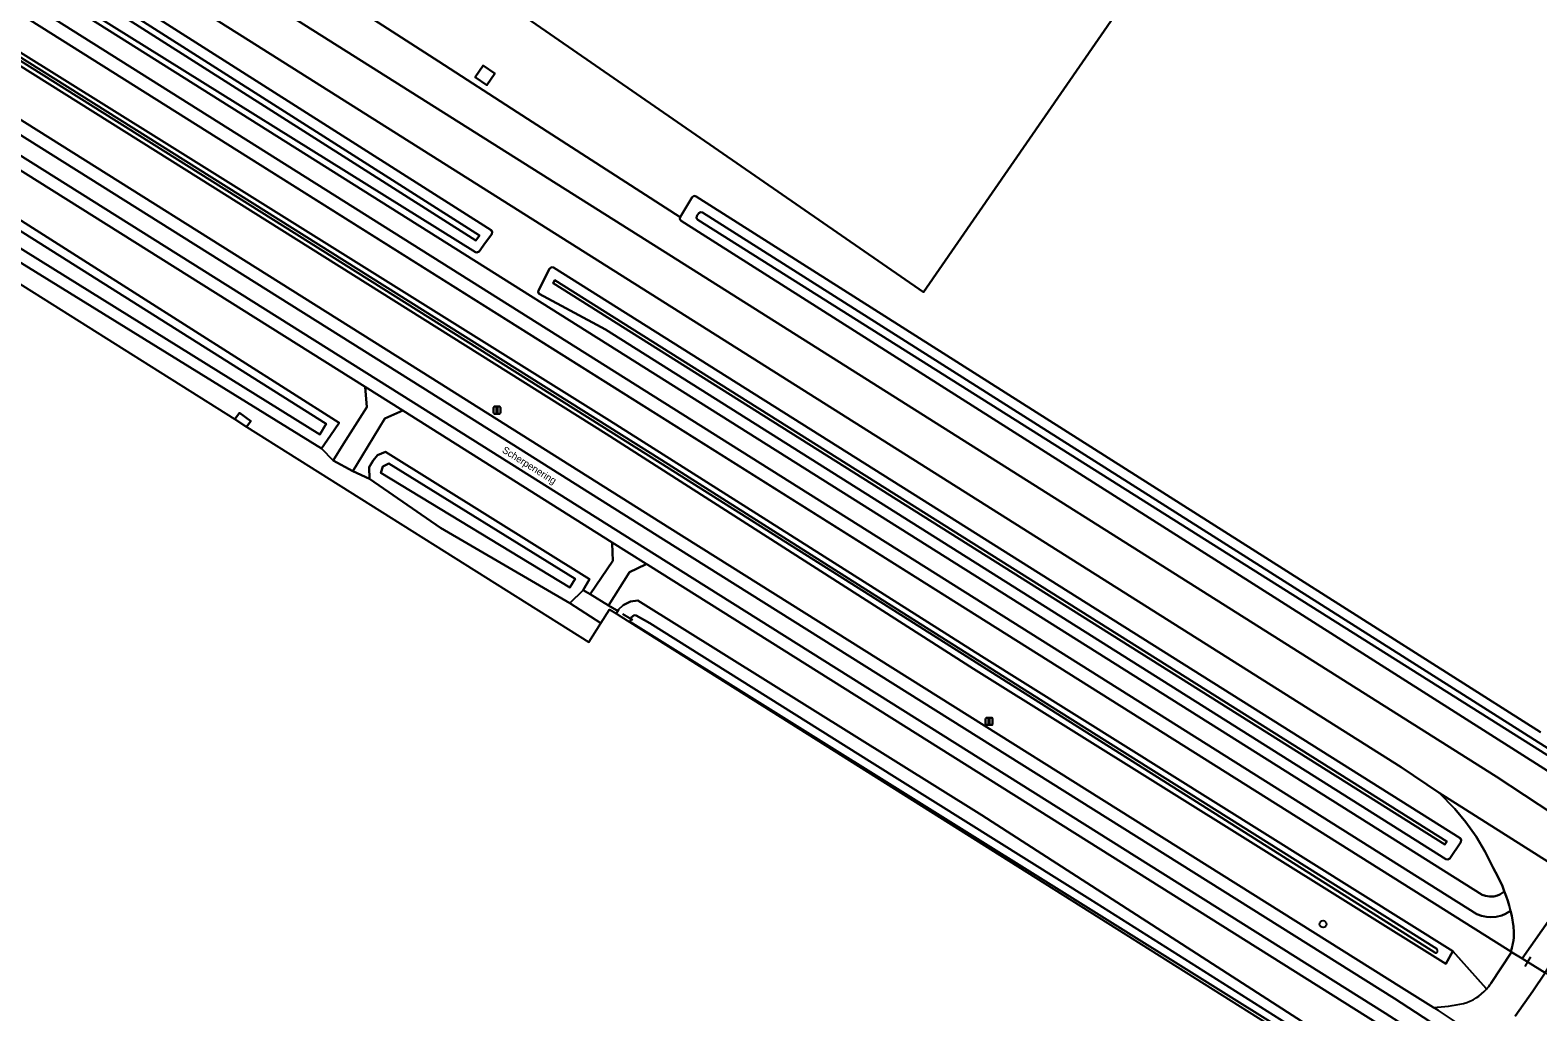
# Model space of a CAD drawing. Extents: x 152881 to 155736, y 382924 to 386919.
# Drawn here: x 153064.6 to 153277.6, y 383016.9 to 383155.6 of the extents above; entities that cross this region are included whole.
import ezdxf

# ---------------------------------------------------------------- set-up
doc = ezdxf.new("R2010")
doc.units = 0
for name, color, linetype in [('IMGEO_Berm_groen', 7, 'Continuous'), ('IMGEO_Boom', 7, 'Continuous'), ('IMGEO_Duiker', 7, 'Continuous'), ('IMGEO_Groenvoorziening', 7, 'Continuous'), ('IMGEO_Hek', 7, 'Continuous'), ('IMGEO_Lichtmast', 7, 'Continuous'), ('IMGEO_Oever', 7, 'Continuous'), ('IMGEO_Openbare_ruimte_label', 7, 'Continuous'), ('IMGEO_Rijbaan_lokaal_gesloten', 7, 'Continuous'), ('IMGEO_Rijbaan_lokaal_open', 7, 'Continuous'), ('IMGEO_Sloot', 7, 'Continuous'), ('IMGEO_Terreindeel_gesloten', 7, 'Continuous'), ('IMGEO_Terreindeel_onvherhard', 7, 'Continuous'), ('IMGEO_Waterloop', 7, 'Continuous')]:
    doc.layers.add(name, color=color, linetype=linetype)

msp = doc.modelspace()

# ---------------------------------------------------------------- linework, layer by layer
at = {"layer": 'IMGEO_Berm_groen'}
msp.add_lwpolyline([(153145.22, 383071.86), (153146.43, 383073.79), (153147.39, 383073.19), (153147.6, 383073.55), (153147.4, 383073.67), (153146.3, 383074.34), (153143.71, 383075.93), (153142.71, 383076.51), (153140.83, 383074.66)], close=True, dxfattribs=at)
at = {"layer": 'IMGEO_Boom'}
msp.add_circle((153247.26, 383029.32), 0.489, dxfattribs=at)
at = {"layer": 'IMGEO_Duiker'}
msp.add_lwpolyline([(153148.25, 383073.16), (153149.66, 383072.31)], dxfattribs=at)
at = {"layer": 'IMGEO_Groenvoorziening'}
for points in [[(153270.96, 383020.95), (153273.9, 383025.38), (153273.81, 383025.44), (153273.05, 383025.91), (153030.73, 383178.33), (152959.64, 383223.14), (152933.46, 383239.65), (152928.97, 383247.39), (152928.17, 383250), (152926.53, 383255.4), (152926.3, 383256.13), (152927.9, 383267.67), (152937.99, 383340.71), (152944.2, 383369.81), (152955.53, 383400.99), (152969.74, 383429.27), (152974.63, 383436.64), (152983.1, 383449.09), (153167.02, 383706.28)], [(153270.36, 383020.15), (153270.3, 383020.23), (153265.62, 383025.5), (153264.61, 383023.7), (153197.89, 383065.4), (153145.97, 383098.58), (153082.25, 383138.58), (153000, 383190.23), (152959.15, 383215.88), (152928.25, 383235.62), (152928.76, 383236.26), (152929.29, 383236.92), (152923.76, 383241.92)], [(152923.76, 383241.92), (152929.29, 383236.92), (152960.62, 383216.52), (153000, 383191.92), (153083.11, 383140.01), (153146.41, 383100.47), (153199.01, 383067.2), (153265.62, 383025.5), (153270.3, 383020.23), (153270.36, 383020.15)], [(152921, 383232.83), (152920.73, 383232.47), (152974.17, 383198.93), (153121.08, 383106.58), (153154.94, 383085.28), (153258.36, 383020.37), (153262.88, 383017.55)], [(153002.4, 383201.71), (153269.76, 383033.47), (153270.23, 383033.3), (153270.78, 383033.2), (153271.4, 383033.23), (153271.92, 383033.36), (153272.25, 383033.51), (153272.67, 383033.78), (153272.88, 383033.96), (153272.61, 383034.66), (153271.96, 383036.05), (153271.63, 383036.68), (153271.29, 383037.28), (153270.17, 383039.54), (153268.88, 383041.71), (153267.46, 383043.72), (153265.89, 383045.63), (153263.65, 383047.85), (153258.32, 383051.48), (153095.4, 383154.22), (153012.06, 383206.63)], [(153247.65, 383200.89), (153190.8, 383118.62), (153092.29, 383186.7)], [(153278.99, 383050.98), (153237.4, 383077.41), (153156.56, 383128.66), (153156.39, 383128.91), (153156.43, 383129.21), (153133.39, 383144.04), (153122.32, 383151.17), (153085.36, 383174.95)], [(153085.36, 383174.95), (153122.32, 383151.17), (153133.39, 383144.04), (153156.43, 383129.21), (153158.13, 383132.01), (153158.38, 383132.19), (153158.69, 383132.14), (153239.69, 383080.75), (153277.97, 383056.46)], [(153083.88, 383168.64), (153153.92, 383124.47), (153271.72, 383050.18), (153279.75, 383044.92)], [(153070.92, 383164.74), (153129.69, 383127.38), (153129.87, 383127.11), (153129.8, 383126.8), (153128.92, 383125.61), (153128.01, 383124.37), (153127.68, 383124.21), (153127.48, 383124.27), (153068.18, 383161.24)], [(153151.62, 383080.21), (153151.5, 383080.15), (153149.27, 383079.03), (153146.3, 383074.34), (153147.4, 383073.67), (153147.6, 383073.55), (153147.71, 383073.75), (153148.36, 383074.38), (153149.4, 383074.91), (153150.43, 383075.06), (153199.05, 383044.71), (153261.96, 383004.15), (153263.75, 383002.45), (153265.3, 383000.65)], [(153259.85, 383011.68), (153260.11, 383012.04), (153255.3, 383015.08), (153151.84, 383080.07), (153151.62, 383080.21)], [(153284.16, 383000), (153285.11, 383013.48), (153285.32, 383016.39), (153286.97, 383014.98), (153287.1, 383017.12), (153279.29, 383022.07), (153278.65, 383022.46), (153276.89, 383019.83), (153274.4, 383016.31)]]:
    msp.add_lwpolyline(points, dxfattribs=at)
for points in [[(153190.8, 383118.62), (153247.65, 383200.89), (153132.48, 383280.48), (153075.62, 383198.22), (153089.84, 383188.39), (153089.92, 383188.51), (153092.37, 383186.82), (153092.29, 383186.7)], [(153270.35, 383030.34), (153269.65, 383030.5), (153268.98, 383030.75), (153000.84, 383199.48), (152960.77, 383224.74), (152959.93, 383223.55), (152959.64, 383223.14), (153030.73, 383178.33), (153273.05, 383025.91), (153273.81, 383025.44), (153273.95, 383025.91), (153274.09, 383026.56), (153274.16, 383027), (153274.21, 383027.44), (153274.23, 383028.21), (153274.18, 383028.98), (153273.93, 383030.47), (153273.74, 383031.21), (153273.05, 383030.78), (153272.51, 383030.56), (153271.72, 383030.36), (153270.97, 383030.3)], [(153000.4, 383175.26), (153000, 383175.07), (152998.15, 383174.21), (152994.7, 383168.72), (152993.1, 383166.16), (152994.67, 383165.11), (152996.32, 383167.7), (152997.95, 383170.27), (153000, 383168.97), (153072.65, 383122.76), (153108.22, 383100.14), (153107, 383098.37), (153105.73, 383096.53), (153107.36, 383094.81), (153108.86, 383097.18), (153112.14, 383102.37), (153111.89, 383105.21)], [(153130.2, 383149.49), (153129.08, 383147.86), (153127.44, 383148.99), (153128.57, 383150.62)], [(153136.5, 383118.37), (153136.36, 383118.6), (153136.39, 383118.86), (153137.96, 383121.92), (153138.21, 383122.13), (153138.53, 383122.08), (153217.59, 383072.33), (153266.62, 383041.47), (153266.8, 383041.22), (153266.74, 383040.91), (153265.17, 383038.6), (153264.92, 383038.43), (153264.63, 383038.48), (153145.85, 383113.34)], [(153117.21, 383101.88), (153114.66, 383100.74), (153111.49, 383095.5), (153110.15, 383093.3), (153112.51, 383092.25), (153112.48, 383093.86), (153113.04, 383094.8), (153113.64, 383095.59), (153114.75, 383096.04), (153143.59, 383078.07), (153142.71, 383076.51), (153143.71, 383075.93), (153146.89, 383080.65), (153146.82, 383083.09), (153146.82, 383083.24)]]:
    msp.add_lwpolyline(points, close=True, dxfattribs=at)
for centre, radius, start, end in [((153265.44, 383024.44), 6.54, 284.7663, 318.893), ((153265.59, 383024.33), 6.35, 318.7416, 327.7708), ((153261.86, 383040.75), 23.22, 272.4991, 283.0433)]:
    msp.add_arc(centre, radius, start, end, dxfattribs=at)
at = {"layer": 'IMGEO_Hek'}
for points in [[(152959.64, 383223.14), (153030.73, 383178.33), (153142.93, 383107.76), (153273.05, 383025.91)], [(153273.05, 383025.91), (153273.81, 383025.44)], [(153273.81, 383025.44), (153275.42, 383024.45)], [(153275.42, 383024.45), (153276.17, 383023.99)], [(153276.56, 383024.63), (153276.17, 383023.99)], [(153276.17, 383023.99), (153275.77, 383023.35)], [(153276.17, 383023.99), (153278.65, 383022.46)]]:
    msp.add_lwpolyline(points, dxfattribs=at)
at = {"layer": 'IMGEO_Lichtmast'}
for p, q in [((153130.03, 383101.53), (153130.03, 383102.33)), ((153130.03, 383102.33), (153130.03, 383101.53)), ((153130.13, 383102.43), (153130.92, 383102.43)), ((153130.92, 383102.43), (153130.13, 383102.43)), ((153130.92, 383101.43), (153130.13, 383101.43)), ((153130.13, 383101.43), (153130.92, 383101.43)), ((153131.02, 383102.33), (153131.02, 383101.53)), ((153131.02, 383101.53), (153131.02, 383102.33)), ((153199.68, 383058.46), (153200.47, 383058.46)), ((153200.47, 383058.46), (153199.68, 383058.46)), ((153199.58, 383057.56), (153199.58, 383058.36)), ((153199.58, 383058.36), (153199.58, 383057.56)), ((153200.47, 383057.46), (153199.68, 383057.46)), ((153199.68, 383057.46), (153200.47, 383057.46)), ((153200.57, 383058.36), (153200.57, 383057.56)), ((153200.57, 383057.56), (153200.57, 383058.36))]:
    msp.add_line(p, q, dxfattribs=at)
for points in [[(153130.45, 383102.31), (153130.6, 383102.31), (153130.6, 383101.56), (153130.45, 383101.56), (153130.45, 383102.31)], [(153200, 383058.33), (153200.15, 383058.33), (153200.15, 383057.58), (153200, 383057.58), (153200, 383058.33)]]:
    msp.add_lwpolyline(points, dxfattribs=at)
for centre, start, end in [((153130.13, 383102.33), 90, 180), ((153130.13, 383102.33), 90, 180), ((153130.13, 383101.53), 180, 270), ((153130.13, 383101.53), 180, 270), ((153130.92, 383102.33), 0, 90), ((153130.92, 383102.33), 360, 90), ((153130.92, 383101.53), 270, 0), ((153130.92, 383101.53), 270, 0), ((153199.68, 383058.36), 90, 180), ((153199.68, 383058.36), 90, 180), ((153200.47, 383058.36), 0, 90), ((153200.47, 383058.36), 360, 90), ((153199.68, 383057.56), 180, 270), ((153199.68, 383057.56), 180, 270), ((153200.47, 383057.56), 270, 0), ((153200.47, 383057.56), 270, 0)]:
    msp.add_arc(centre, 0.1, start, end, dxfattribs=at)
at = {"layer": 'IMGEO_Oever'}
for points in [[(152929.29, 383236.92), (152928.76, 383236.26), (152928.25, 383235.62), (152959.15, 383215.88), (153000, 383190.23), (153082.25, 383138.58), (153145.97, 383098.58), (153197.89, 383065.4), (153264.61, 383023.7), (153265.62, 383025.5), (153199.01, 383067.2), (153146.41, 383100.47), (153083.11, 383140.01), (153000, 383191.92), (152960.62, 383216.52)], [(153107, 383098.37), (153108.22, 383100.14), (153072.65, 383122.76), (153000, 383168.97), (152997.95, 383170.27), (152996.32, 383167.7), (152994.67, 383165.11), (152995.37, 383164.68), (152998.84, 383162.53), (153105.73, 383096.53)], [(152998.64, 383167.94), (153106.4, 383099.98), (153105.5, 383098.51), (153002.71, 383162.42), (152997.61, 383166.25)], [(153136.5, 383118.37), (153145.85, 383113.34), (153264.63, 383038.48), (153264.92, 383038.43), (153265.17, 383038.6), (153266.74, 383040.91), (153266.8, 383041.22), (153266.62, 383041.47), (153217.59, 383072.33), (153138.53, 383122.08), (153138.21, 383122.13), (153137.96, 383121.92), (153136.39, 383118.86), (153136.36, 383118.6)], [(153214.55, 383071.99), (153138.48, 383119.87), (153138.71, 383120.32), (153215.57, 383071.94), (153264.74, 383041), (153264.46, 383040.58)], [(153142.71, 383076.51), (153143.59, 383078.07), (153114.75, 383096.04), (153113.64, 383095.59), (153113.04, 383094.8), (153112.48, 383093.86), (153112.51, 383092.25), (153122.53, 383085.33), (153140.83, 383074.66)], [(153115.24, 383094.39), (153141.57, 383078.08), (153140.81, 383076.86), (153114.13, 383093.08), (153114.4, 383093.98)]]:
    msp.add_lwpolyline(points, close=True, dxfattribs=at)
for points in [[(153263.04, 383025.3), (153208.01, 383060.1), (153183.34, 383075.7), (153153.59, 383094.51), (153050.85, 383159.03), (152960.36, 383215.82), (152940.52, 383228.58), (152929.21, 383235.97)], [(152929.44, 383236.3), (152940.74, 383228.92), (152960.57, 383216.16), (153051.06, 383159.37), (153153.81, 383094.85), (153183.55, 383076.04), (153208.22, 383060.44), (153263.32, 383025.81)], [(153071.38, 383162.67), (153128.07, 383126.63), (153127.53, 383125.89), (153003.11, 383204.99)], [(153068.18, 383161.24), (153127.48, 383124.27), (153127.68, 383124.21), (153128.01, 383124.37), (153128.92, 383125.61), (153129.8, 383126.8), (153129.87, 383127.11), (153129.69, 383127.38), (153070.92, 383164.74)], [(153277.97, 383056.46), (153239.69, 383080.75), (153158.69, 383132.14), (153158.38, 383132.19), (153158.13, 383132.01), (153156.43, 383129.21), (153156.39, 383128.91), (153156.56, 383128.66), (153237.4, 383077.41), (153278.99, 383050.98)], [(153280.17, 383052.44), (153239.55, 383078.01), (153158.9, 383128.82), (153158.72, 383129.08), (153158.79, 383129.4), (153159.04, 383129.74), (153159.29, 383129.9), (153159.58, 383129.84), (153280.49, 383053.22)], [(153265.3, 383000.65), (153263.75, 383002.45), (153261.96, 383004.15), (153199.05, 383044.71), (153150.43, 383075.06), (153149.4, 383074.91), (153148.36, 383074.38), (153147.71, 383073.75), (153147.6, 383073.55), (153147.39, 383073.19)], [(153147.39, 383073.19), (153148.03, 383072.78), (153251.7, 383007.5)], [(153250.5, 383008.87), (153233.94, 383019.21), (153149.33, 383072.05), (153149.48, 383072.63), (153149.92, 383072.95), (153150.18, 383072.91), (153152.11, 383071.85), (153183.57, 383052.11), (153214.32, 383032.84), (153242.93, 383014.75)]]:
    msp.add_lwpolyline(points, dxfattribs=at)
msp.add_arc((153263.17, 383025.56), 0.292, 243.1895, 58.0522, dxfattribs=at)
at = {"layer": 'IMGEO_Rijbaan_lokaal_gesloten'}
for points in [[(153262.35, 383015.54), (153257.35, 383018.82), (153154.08, 383083.68), (153120.06, 383105.09), (152973.17, 383197.41), (152919.8, 383231.03)], [(152919.8, 383231.03), (152973.17, 383197.41), (153120.06, 383105.09), (153154.08, 383083.68), (153257.35, 383018.82), (153262.35, 383015.54)], [(153262.88, 383017.55), (153258.36, 383020.37), (153154.94, 383085.28), (153121.08, 383106.58), (152974.17, 383198.93), (152920.73, 383232.47)], [(152915.19, 383228.97), (152923.02, 383223.76), (152966.1, 383196.84), (152966.22, 383196.76), (152970.72, 383193.91), (152970.98, 383193.75), (152995.67, 383178.24), (153000.4, 383175.26), (153111.89, 383105.21), (153117.21, 383101.88), (153146.82, 383083.24), (153151.62, 383080.21), (153151.84, 383080.07), (153255.3, 383015.08), (153260.11, 383012.04)], [(153261.05, 383013.52), (153256.04, 383016.73), (153152.77, 383081.6), (153118.71, 383103), (152971.92, 383195.29), (152918.11, 383229.16)], [(152918.11, 383229.16), (152971.92, 383195.29), (153118.71, 383103), (153152.77, 383081.6), (153256.04, 383016.73), (153261.05, 383013.52)], [(153012.06, 383206.63), (153095.4, 383154.22), (153258.32, 383051.48), (153263.65, 383047.85), (153279.06, 383038.14)], [(153279.75, 383044.92), (153271.72, 383050.18), (153153.92, 383124.47), (153083.88, 383168.64)]]:
    msp.add_lwpolyline(points, dxfattribs=at)
msp.add_lwpolyline([(152960.77, 383224.74), (153000.84, 383199.48), (153268.98, 383030.75), (153269.65, 383030.5), (153270.35, 383030.34), (153270.97, 383030.3), (153271.72, 383030.36), (153272.51, 383030.56), (153273.05, 383030.78), (153273.74, 383031.21), (153273.57, 383031.94), (153273.37, 383032.6), (153273.15, 383033.26), (153272.88, 383033.96), (153272.67, 383033.78), (153272.25, 383033.51), (153271.92, 383033.36), (153271.4, 383033.23), (153270.78, 383033.2), (153270.23, 383033.3), (153269.76, 383033.47), (153002.4, 383201.71), (152962.33, 383226.97)], close=True, dxfattribs=at)
msp.add_arc((153248.03, 382992.08), 29.48, 33.5771, 59.7661, dxfattribs=at)
at = {"layer": 'IMGEO_Rijbaan_lokaal_open'}
for points in [[(153114.66, 383100.74), (153117.21, 383101.88), (153111.89, 383105.21), (153112.14, 383102.37), (153108.86, 383097.18), (153107.36, 383094.81), (153110.15, 383093.3), (153111.49, 383095.5)], [(153149.27, 383079.03), (153151.5, 383080.15), (153151.62, 383080.21), (153146.82, 383083.24), (153146.82, 383083.09), (153146.89, 383080.65), (153143.71, 383075.93), (153146.3, 383074.34)], [(153295.4, 383033.17), (153293.31, 383033.44), (153292.34, 383033.59), (153291.34, 383033.77), (153289.77, 383034.09), (153287.83, 383034.55), (153286.46, 383034.92), (153285.81, 383035.12), (153283.51, 383036), (153279.42, 383030.17), (153275.42, 383024.45), (153276.17, 383023.99), (153278.65, 383022.46), (153279.06, 383023.14), (153281.87, 383025.55), (153282.96, 383026.33), (153284.44, 383027.5), (153285.65, 383028.26), (153286.88, 383029.03), (153287.16, 383029.2), (153290.83, 383031.1), (153293.37, 383032.24)]]:
    msp.add_lwpolyline(points, close=True, dxfattribs=at)
for points in [[(153279.06, 383038.14), (153263.65, 383047.85), (153265.89, 383045.63), (153267.46, 383043.72), (153268.88, 383041.71), (153270.17, 383039.54), (153271.29, 383037.28), (153271.63, 383036.68), (153271.96, 383036.05), (153272.61, 383034.66), (153272.88, 383033.96), (153273.15, 383033.26), (153273.37, 383032.6), (153273.57, 383031.94), (153273.74, 383031.21), (153273.93, 383030.47), (153274.18, 383028.98), (153274.23, 383028.21), (153274.21, 383027.44), (153274.16, 383027), (153274.09, 383026.56), (153273.95, 383025.91), (153273.81, 383025.44), (153273.9, 383025.38), (153275.42, 383024.45), (153279.42, 383030.17)], [(153276.89, 383019.83), (153278.65, 383022.46), (153276.17, 383023.99), (153275.42, 383024.45), (153273.9, 383025.38), (153270.96, 383020.95)], [(153274.4, 383016.31), (153276.89, 383019.83)]]:
    msp.add_lwpolyline(points, dxfattribs=at)
for centre, radius, start, end in [((153265.44, 383024.44), 6.54, 284.7663, 318.893), ((153265.59, 383024.33), 6.35, 318.7416, 327.7708), ((153261.86, 383040.75), 23.22, 272.4991, 283.0433), ((153248.03, 382992.08), 29.48, 33.5771, 59.7661)]:
    msp.add_arc(centre, radius, start, end, dxfattribs=at)
at = {"layer": 'IMGEO_Sloot'}
msp.add_lwpolyline([(153242.93, 383014.75), (153214.32, 383032.84), (153183.57, 383052.11), (153152.11, 383071.85), (153150.18, 383072.91), (153149.92, 383072.95), (153149.48, 383072.63), (153149.33, 383072.05), (153233.94, 383019.21), (153250.5, 383008.87)], dxfattribs=at)
at = {"layer": 'IMGEO_Terreindeel_gesloten'}
for points in [[(153127.44, 383148.99), (153129.08, 383147.86), (153130.2, 383149.49), (153128.57, 383150.62)], [(153093.48, 383100.64), (153095.15, 383099.58), (153095.74, 383100.4), (153094.13, 383101.55)]]:
    msp.add_lwpolyline(points, close=True, dxfattribs=at)
at = {"layer": 'IMGEO_Terreindeel_onvherhard'}
msp.add_lwpolyline([(153095.15, 383099.58), (153143.5, 383069.14), (153145.22, 383071.86), (153140.83, 383074.66), (153122.53, 383085.33), (153112.51, 383092.25), (153110.15, 383093.3), (153107.36, 383094.81), (153105.73, 383096.53), (152998.84, 383162.53), (152995.37, 383164.68), (152994.98, 383162.66), (153000, 383159.5), (153093.48, 383100.64), (153094.13, 383101.55), (153095.74, 383100.4)], close=True, dxfattribs=at)
at = {"layer": 'IMGEO_Waterloop'}
for points in [[(152929.21, 383235.97), (152940.52, 383228.58), (152960.36, 383215.82), (153050.85, 383159.03), (153153.59, 383094.51), (153183.34, 383075.7), (153208.01, 383060.1), (153263.04, 383025.3)], [(153263.32, 383025.81), (153208.22, 383060.44), (153183.55, 383076.04), (153153.81, 383094.85), (153051.06, 383159.37), (152960.57, 383216.16), (152940.74, 383228.92), (152929.44, 383236.3)], [(153003.11, 383204.99), (153127.53, 383125.89), (153128.07, 383126.63), (153071.38, 383162.67)]]:
    msp.add_lwpolyline(points, dxfattribs=at)
for points in [[(152998.64, 383167.94), (152997.61, 383166.25), (153002.71, 383162.42), (153105.5, 383098.51), (153106.4, 383099.98)], [(153291.26, 383047.07), (153291.83, 383047.88), (153288.97, 383048.78), (153286.5, 383049.88), (153280.49, 383053.22), (153159.58, 383129.84), (153159.29, 383129.9), (153159.04, 383129.74), (153158.79, 383129.4), (153158.72, 383129.08), (153158.9, 383128.82), (153239.55, 383078.01), (153280.17, 383052.44), (153283.99, 383050.38), (153286.34, 383049), (153288.83, 383047.88)], [(153214.55, 383071.99), (153264.46, 383040.58), (153264.74, 383041), (153215.57, 383071.94), (153138.71, 383120.32), (153138.48, 383119.87)], [(153115.24, 383094.39), (153114.4, 383093.98), (153114.13, 383093.08), (153140.81, 383076.86), (153141.57, 383078.08)]]:
    msp.add_lwpolyline(points, close=True, dxfattribs=at)
msp.add_arc((153263.17, 383025.56), 0.292, 243.1895, 58.0522, dxfattribs=at)

# ---------------------------------------------------------------- texts
at = {"layer": 'IMGEO_Openbare_ruimte_label'}
msp.add_text('Scherpenering', height=1, rotation=327.8671, dxfattribs=at).set_placement((153131.16, 383096.04))

doc.saveas('drawing.dxf')
